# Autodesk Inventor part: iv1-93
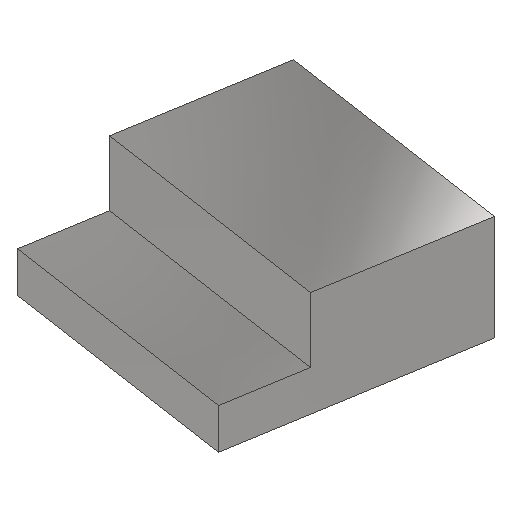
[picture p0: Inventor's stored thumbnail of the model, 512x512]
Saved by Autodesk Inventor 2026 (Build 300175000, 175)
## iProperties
Created: 2004-09
Part Number: iv1-93
Document SubType Name: Modeling
Designer: Lars Bertram Pedersen
Manufacturer: Standard
Standards Organization: Custom
Material: Steel, Mild
Density: 7.85 g/cm^3
Appearance: Semi-Polished
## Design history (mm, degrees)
sketch "Sketch1"
  geometry: L1 (-60, 0)-(0, 0); L2 (0, 0)-(0, 10); L3 (0, 10)-(-20, 10); L4 (-20, 10)-(-20, 26); L5 (-20, 26)-(-60, 26); L6 (-60, 26)-(-60, 0); 1 further point
  constraints: 12 end point, 3 perpendicular, 2 parallel, 1 coincident, 1 horizontal
  dimensions: "d0" = 60 distance of L1.start L1.end; "d1" = 10 distance of L1.end L2.end; "d2" = 16 distance of L3.end L4.end; "d3" = 40 distance of L4.end L5.end
extrude "Extrusion1" new body sketch "Sketch1" distance "d4" = 60; taper "d5" = 0 deg
body "Solid1"
